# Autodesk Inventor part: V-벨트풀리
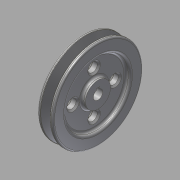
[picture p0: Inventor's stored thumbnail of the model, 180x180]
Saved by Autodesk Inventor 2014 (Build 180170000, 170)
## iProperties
Created: 2015-09
Part Number: V-벨트풀리
Material: 강철, 연강
Document SubType Name: Modeling
Designer: mduedu
Density: 1 g/cm^3
Appearance: 강철
Author: mduedu
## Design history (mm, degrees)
sketch "스케치1"
  geometry: L1 (-10, 0)-(10, 0); L2 (-10, 0)-(-10, 57.5); L3 (-10, 57.5)-(-6.062, 57.5); L4 (-6.062, 57.5)-(-2.001, 45); L5 (-2.001, 45)-(2.001, 45); L6 (2.001, 45)-(6.062, 57.5); L7 (6.062, 57.5)-(10, 57.5); L8 (10, 57.5)-(10, 0); L9 (0, 0)-(0, 45); L10 (-10, 53)-(10, 53); 3 further points
  constraints: 20 end point, 6 point on line, 3 perpendicular, 2 midpoint, 2 parallel, 2 symmetric about line, 1 coincident, 1 collinear, 1 equal length, 1 horizontal, 1 vertical, 1 vertical alignment
  dimensions: "d0" = 20 distance between parallel lines of L8 L2; "d2" = 115 diameter of L3 L1; "d5" = 8 distance between parallel lines of L5 L10; "d6" = 9.2 distance of point (4.6, 53) point (-4.6, 53); "d7" = 36 deg angle of L6 L4; "d40" = 4.5 distance between parallel lines of L10 L3
revolve "회전1" sketch "스케치1" stored, may be unused: angle "d8" = 90 deg
sketch "스케치2"
  geometry: C1 r 16 at (0, 0); C2 r 41 at (0, 0); 1 further point
  constraints: 2 centre point, 2 coincident
  dimensions: "d9" = 32 diameter of C1; "d41" = 82 diameter of C2
extrude "돌출5" cut sketch "스케치2" distance "d42" = 5; taper "d43" = 0 deg
hole "구멍2" diameter "d46" = 12; stored, may be unused: countersink angle "d50" = 90 deg, drill point angle "d52" = 118 deg; dims "d44" = 10, "d45" = 10, "d47" = 6, "d48" = 4, "d49" = 2, "d51" = 8
sketch "스케치8"
  geometry: L1 (-2, 5.657)-(2, 5.657); L2 (2, 5.657)-(2, 7.8); L3 (2, 7.8)-(-2, 7.8); L4 (-2, 7.8)-(-2, 5.657); A1 r 6 centre (0, 0) between (-2, 5.657) and (2, 5.657) reference; 1 further point
  constraints: 8 end point, 2 parallel, 2 point on circle, 1 horizontal, 1 perpendicular
  dimensions: "d53" = 4 distance of L2.end L3.end; "d55" = 13.8 dimension on A1 L3
extrude "돌출6" cut sketch "스케치8" stored distance "d56" = 5; taper "d57" = 0 deg
sketch "스케치9"
  geometry: C1 r 6 at (0, 27); 1 further point
  constraints: 1 centre point, 1 vertical alignment
  dimensions: "d61" = 12 diameter of C1; "d62" = 27 distance of C1.centre point (0, 0)
extrude "돌출7" cut sketch "스케치9" stored distance "d63" = 5; taper "d64" = 0 deg
chamfer "모따기3" distance "d65" = 2; stored, may be unused: second distance "d66" = 2, angle "d67" = 45 deg
fillet "모깎기5" dims "d71" = 2, "d72" = 1, "d73" = 0.5
fillet "모깎기6" dims "d74" = 3
fillet "모깎기7" dims "d75" = 3
fillet "모깎기8" dims "d76" = 3
sketch "스케치10"
  geometry: C1 r 47.5 at (0, 0); 1 further point
  constraints: 1 centre point, 1 coincident, 1 other
  dimensions: "d77" = 95 diameter of C1
extrude "돌출8" join sketch "스케치10" distance "d80" = 0.5; taper "d81" = 0 deg
node "솔리드1"
mirror "대칭2"
pattern_circular "원형 패턴1" dims "d69" = 360 deg
